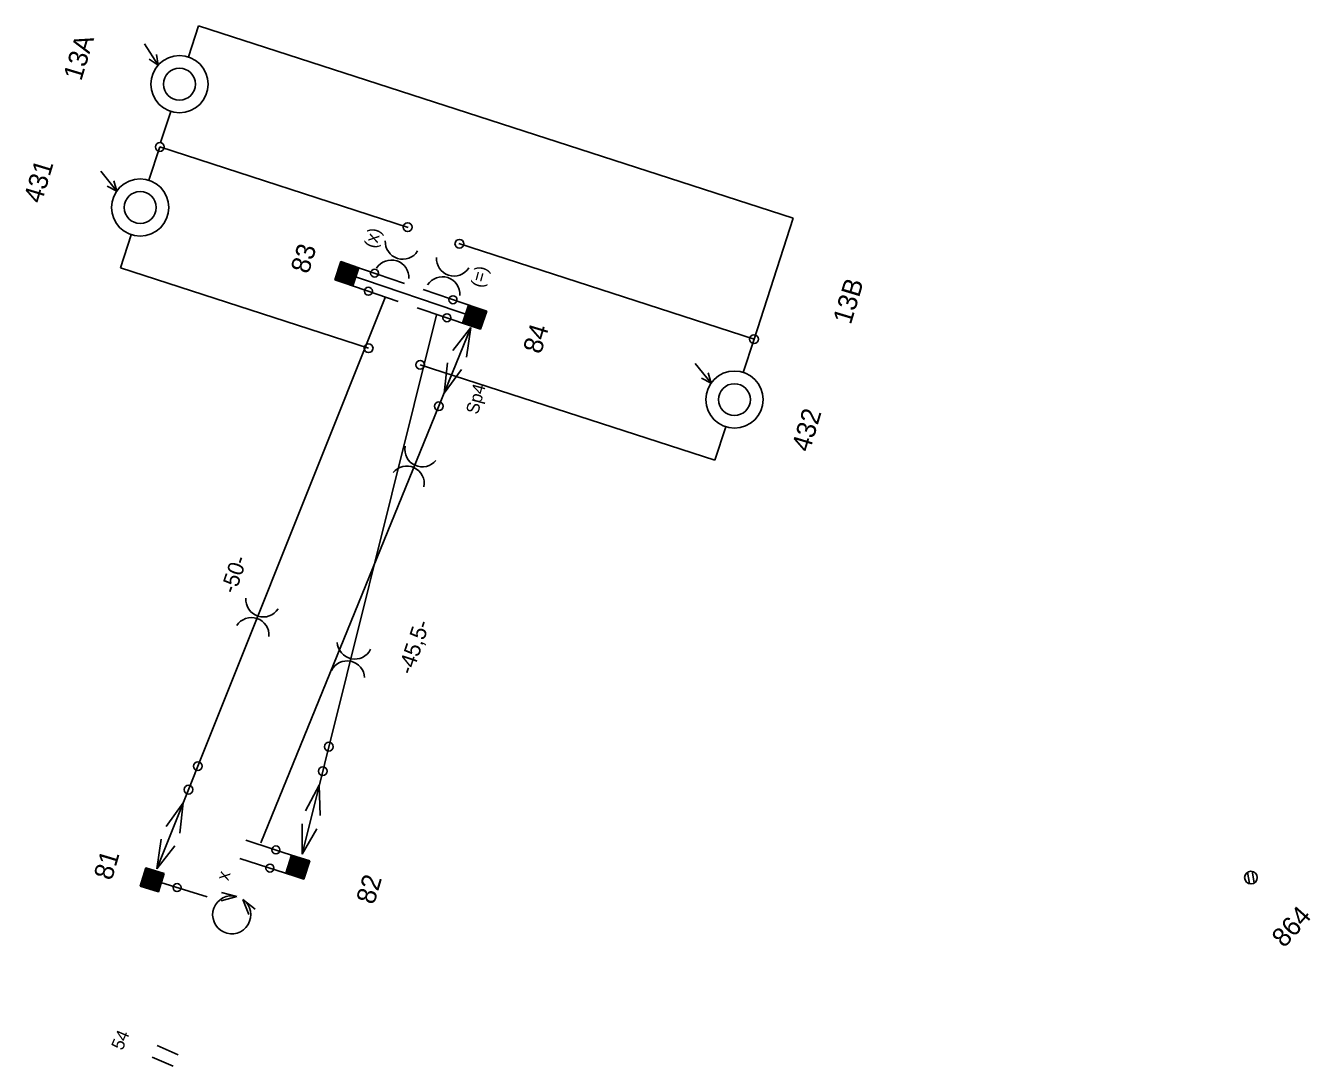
# Model space of a CAD drawing. Extents: x -595867 to -593796, y -1159595 to -1157495.
# Drawn here: x -594654.2 to -594553.2, y -1157682.6 to -1157600.8 of the extents above; entities that cross this region are included whole.
import ezdxf

# ---------------------------------------------------------------- set-up
doc = ezdxf.new("R2010")
doc.units = 0
doc.layers.add('BVK_kanalizace_destova_nova', color=7, linetype='Continuous')
doc.layers.add('BVK_kanalizace_jednotna_nova', color=7, linetype='Continuous')

# ---------------------------------------------------------------- blocks, each defined once
blk = doc.blocks.new('st_bp')
for p, q in [((0.0075, 0.0075), (-0.0075, 0.0075)), ((-0.0075, 0.0075), (-0.0075, -0.0075)), ((-0.0075, -0.0075), (0.0075, 0.0075)), ((-0.0075, -0.0071), (0.0071, 0.0075)), ((-0.0075, -0.0067), (0.0067, 0.0075)), ((-0.0075, -0.0062), (0.0062, 0.0075)), ((-0.0075, -0.0058), (0.0058, 0.0075)), ((-0.0075, -0.0054), (0.0054, 0.0075)), ((-0.0075, -0.005), (0.005, 0.0075)), ((-0.0075, -0.0045), (0.0045, 0.0075)), ((-0.0075, -0.0041), (0.0041, 0.0075)), ((-0.0075, -0.0037), (0.0037, 0.0075)), ((-0.0075, -0.0033), (0.0033, 0.0075)), ((-0.0075, -0.0028), (0.0028, 0.0075)), ((-0.0075, -0.0024), (0.0024, 0.0075)), ((-0.0075, -0.002), (0.002, 0.0075)), ((-0.0075, -0.0016), (0.0016, 0.0075)), ((-0.0075, -0.0011), (0.0011, 0.0075)), ((-0.0075, -0.0007), (0.0007, 0.0075)), ((-0.0075, -0.0003), (0.0003, 0.0075)), ((-0.0075, 0.0001), (-0.0001, 0.0075)), ((-0.0075, 0.0006), (-0.0006, 0.0075)), ((-0.0075, 0.001), (-0.001, 0.0075)), ((-0.0075, 0.0014), (-0.0014, 0.0075)), ((-0.0075, 0.0018), (-0.0018, 0.0075)), ((-0.0075, 0.0023), (-0.0023, 0.0075)), ((-0.0075, 0.0027), (-0.0027, 0.0075)), ((-0.0075, 0.0031), (-0.0031, 0.0075)), ((-0.0075, 0.0035), (-0.0035, 0.0075)), ((-0.0075, 0.004), (-0.004, 0.0075)), ((-0.0075, 0.0044), (-0.0044, 0.0075)), ((-0.0075, 0.0048), (-0.0048, 0.0075)), ((-0.0075, 0.0052), (-0.0052, 0.0075)), ((-0.0075, 0.0057), (-0.0057, 0.0075)), ((-0.0075, 0.0061), (-0.0061, 0.0075)), ((-0.0075, 0.0065), (-0.0065, 0.0075)), ((-0.0075, 0.0069), (-0.0069, 0.0075)), ((-0.0075, 0.0073), (-0.0073, 0.0075)), ((-0.0071, -0.0075), (0.0075, 0.0071)), ((-0.0067, -0.0075), (0.0075, 0.0067)), ((-0.0062, -0.0075), (0.0075, 0.0062)), ((-0.0058, -0.0075), (0.0075, 0.0058)), ((-0.0054, -0.0075), (0.0075, 0.0054)), ((-0.005, -0.0075), (0.0075, 0.005)), ((-0.0045, -0.0075), (0.0075, 0.0045)), ((-0.0041, -0.0075), (0.0075, 0.0041)), ((-0.0037, -0.0075), (0.0075, 0.0037)), ((-0.0033, -0.0075), (0.0075, 0.0033)), ((-0.0028, -0.0075), (0.0075, 0.0028)), ((-0.0024, -0.0075), (0.0075, 0.0024)), ((-0.002, -0.0075), (0.0075, 0.002)), ((-0.0016, -0.0075), (0.0075, 0.0016)), ((-0.0011, -0.0075), (0.0075, 0.0011)), ((-0.0007, -0.0075), (0.0075, 0.0007)), ((-0.0003, -0.0075), (0.0075, 0.0003)), ((0.0075, -0.0075), (0.0075, 0.0075)), ((-0.0075, -0.0075), (0.0075, -0.0075)), ((0.0001, -0.0075), (0.0075, -0.0001)), ((0.0006, -0.0075), (0.0075, -0.0006)), ((0.001, -0.0075), (0.0075, -0.001)), ((0.0014, -0.0075), (0.0075, -0.0014)), ((0.0018, -0.0075), (0.0075, -0.0018)), ((0.0023, -0.0075), (0.0075, -0.0023)), ((0.0027, -0.0075), (0.0075, -0.0027)), ((0.0031, -0.0075), (0.0075, -0.0031)), ((0.0035, -0.0075), (0.0075, -0.0035)), ((0.004, -0.0075), (0.0075, -0.004)), ((0.0044, -0.0075), (0.0075, -0.0044)), ((0.0048, -0.0075), (0.0075, -0.0048)), ((0.0052, -0.0075), (0.0075, -0.0052)), ((0.0057, -0.0075), (0.0075, -0.0057)), ((0.0061, -0.0075), (0.0075, -0.0061)), ((0.0065, -0.0075), (0.0075, -0.0065)), ((0.0069, -0.0075), (0.0075, -0.0069)), ((0.0073, -0.0075), (0.0075, -0.0073))]:
    blk.add_line(p, q)
blk = doc.blocks.new('st_tecka')
blk.add_circle((0, 0), 0.00314)
blk = doc.blocks.new('st1k_bp')
blk.add_line((0, 0), (0.0453, 0))
blk.add_blockref('st_bp', (0, 0))
at = {"rotation": 90}
blk.add_blockref('st_tecka', (0.0205, 0), dxfattribs=at)
blk = doc.blocks.new('st2k_bp')
for p, q in [((0, 0.0075), (0.0453, 0.0075)), ((0, -0.0075), (0.0453, -0.0075))]:
    blk.add_line(p, q)
at = {"rotation": 90}
for p in [(0.0205, 0.0075), (0.0205, -0.0075)]:
    blk.add_blockref('st_tecka', p, dxfattribs=at)
blk.add_blockref('st_bp', (0, 0))
blk = doc.blocks.new('pol_sipk')
for q in [(0.0257, 0.0306), (0.0048, 0.0163), (0.0152, 0.0076)]:
    blk.add_line((0, 0), q)
blk = doc.blocks.new('odp_mzap')
for radius in [0.045, 0.025]:
    blk.add_circle((0, 0), radius)
blk.add_blockref('pol_sipk', (0.0179, 0.0413))
blk = doc.blocks.new('pol_izol')
for centre, start, end in [((-0.0148, 0), 284.4047, 75.5953), ((0.0148, 0), 104.4047, 255.5953)]:
    blk.add_arc(centre, 0.0138, start, end)
blk = doc.blocks.new('kotv_tecka')
blk.add_circle((0, 0), 0.00345)
blk = doc.blocks.new('kotv_poh')
for p, q in [((-0.0558, 0), (-0.0328, 0.0065)), ((-0.0558, 0), (-0.0336, -0.0056)), ((0, 0), (-0.023, -0.0056))]:
    blk.add_line(p, q)
blk.add_lwpolyline([(0, 0), (-0.0221, 0.0064)])
for p in [(-0.087, 0), (-0.0671, 0)]:
    blk.add_blockref('kotv_tecka', p)
blk = doc.blocks.new('pol_sipka2')
for q in [(0.0123, 0.003), (0.0118, -0.0034)]:
    blk.add_line((0, 0), q)
blk = doc.blocks.new('pol_delic')
for p, q in [((-0.005, -0.009), (-0.005, 0.009)), ((0.005, -0.009), (0.005, 0.009))]:
    blk.add_line(p, q)
blk = doc.blocks.new('kotv_polok')
for p, q in [((-0.0558, 0), (-0.0328, 0.0065)), ((-0.0558, 0), (-0.0336, -0.0056)), ((0, 0), (-0.023, -0.0056))]:
    blk.add_line(p, q)
blk.add_lwpolyline([(0, 0), (-0.0221, 0.0064)])
blk.add_blockref('kotv_tecka', (-0.067, 0))
blk = doc.blocks.new('odp_mvyp')
for radius in [0.045, 0.025]:
    blk.add_circle((0, 0), radius)
blk.add_blockref('pol_sipk', (0.0179, 0.0413))

msp = doc.modelspace()

# ---------------------------------------------------------------- linework, layer by layer
at = {"layer": 'BVK_kanalizace_destova_nova'}
for p, q in [((-594641.45, -1157603.25), (-594640.66, -1157600.79)), ((-594593.87, -1157615.93), (-594640.66, -1157600.79)), ((-594643.63, -1157609.99), (-594642.84, -1157607.53)), ((-594644.55, -1157612.95), (-594643.7, -1157610.33)), ((-594643.7, -1157610.33), (-594624.17, -1157616.65)), ((-594596.95, -1157625.45), (-594593.87, -1157615.93)), ((-594646.78, -1157619.84), (-594645.94, -1157617.23)), ((-594596.95, -1157625.45), (-594620.17, -1157617.93)), ((-594627.27, -1157626.16), (-594646.78, -1157619.84)), ((-594625.98, -1157622.18), (-594643.93, -1157667.11)), ((-594621.93, -1157623.52), (-594632.5, -1157665.94)), ((-594635.75, -1157665.06), (-594619.22, -1157624.52)), ((-594597.8, -1157628.06), (-594596.95, -1157625.45)), ((-594623.21, -1157627.46), (-594600.03, -1157634.96)), ((-594600.03, -1157634.96), (-594599.18, -1157632.34))]:
    msp.add_line(p, q, dxfattribs=at)
msp.add_arc((-594638.04, -1157670.72), 1.5, 74.9327, 53.7464, dxfattribs=at)
at = {"layer": 'BVK_kanalizace_jednotna_nova'}
for p, q in [((-594628.35, -1157619.98), (-594629.6, -1157620.63)), ((-594628.85, -1157619.82), (-594629.45, -1157620.12)), ((-594628.51, -1157620.48), (-594629.1, -1157620.79)), ((-594618.3, -1157623.39), (-594619.56, -1157624.03)), ((-594618.8, -1157623.23), (-594619.4, -1157623.53)), ((-594618.47, -1157623.9), (-594619.05, -1157624.19)), ((-594632.72, -1157666.49), (-594633.32, -1157666.79)), ((-594644.17, -1157667.49), (-594644.77, -1157667.79)), ((-594632.22, -1157666.66), (-594633.48, -1157667.29)), ((-594632.39, -1157667.16), (-594632.98, -1157667.45)), ((-594557.97, -1157668.27), (-594558.13, -1157667.37)), ((-594557.6, -1157668.22), (-594557.77, -1157667.3)), ((-594643.67, -1157667.65), (-594644.93, -1157668.29)), ((-594643.83, -1157668.15), (-594644.42, -1157668.45))]:
    msp.add_line(p, q, dxfattribs=at)
for points in [[(-594628.65, -1157620.93), (-594629.61, -1157620.63), (-594629.3, -1157619.67), (-594628.35, -1157619.98)], [(-594618.61, -1157624.34), (-594619.56, -1157624.03), (-594619.25, -1157623.08), (-594618.3, -1157623.39)], [(-594632.53, -1157667.6), (-594633.48, -1157667.29), (-594633.17, -1157666.34), (-594632.22, -1157666.65)], [(-594643.98, -1157668.6), (-594644.93, -1157668.29), (-594644.62, -1157667.34), (-594643.67, -1157667.65)]]:
    msp.add_lwpolyline(points, close=True, dxfattribs=at)
for points in [[(-594628.65, -1157620.93), (-594629.61, -1157620.63), (-594629.3, -1157619.67), (-594628.35, -1157619.98), (-594628.65, -1157620.93)], [(-594628.98, -1157620.3), (-594618.93, -1157623.71)], [(-594618.61, -1157624.34), (-594619.56, -1157624.03), (-594619.25, -1157623.08), (-594618.3, -1157623.39), (-594618.61, -1157624.34)], [(-594632.53, -1157667.6), (-594633.48, -1157667.29), (-594633.17, -1157666.34), (-594632.22, -1157666.65), (-594632.53, -1157667.6)], [(-594643.98, -1157668.6), (-594644.93, -1157668.29), (-594644.62, -1157667.34), (-594643.67, -1157667.65), (-594643.98, -1157668.6)]]:
    msp.add_lwpolyline(points, dxfattribs=at)
msp.add_circle((-594557.86, -1157667.79), 0.5, dxfattribs=at)
msp.add_circle((-594557.86, -1157667.79), 0.5, dxfattribs=at)

# ---------------------------------------------------------------- block references
at = {"layer": 'BVK_kanalizace_destova_nova'}
for name, p, xscale, yscale, rotation in [('odp_mvyp', (-594642.15, -1157605.39), 50.00000000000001, 49.99999999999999, 72.06723553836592), ('kotv_tecka', (-594643.7, -1157610.33), 100, 100, 73.06723553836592), ('odp_mzap', (-594645.24, -1157615.09), 50, 50, 78.51685128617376), ('kotv_tecka', (-594624.2, -1157616.64), 100, 100, 73.06723553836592), ('pol_izol', (-594625.03, -1157619.19), 100.00000000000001, 99.99999999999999, 72.42210460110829), ('kotv_tecka', (-594620.13, -1157617.94), 100, 100, 73.06723553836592), ('st2k_bp', (-594628.98, -1157620.3), 100, 100, -18.916669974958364), ('pol_izol', (-594621.01, -1157620.51), 100.00000000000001, 99.99999999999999, 72.11776305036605), ('st2k_bp', (-594618.93, -1157623.71), 100, 100, 161.3658048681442), ('kotv_polok', (-594619.22, -1157624.52), 100.00000000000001, 99.99999999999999, 67.81291349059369), ('kotv_tecka', (-594596.95, -1157625.45), 100, 100, 73.06723553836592), ('kotv_tecka', (-594627.27, -1157626.16), 100, 100, 73.06723553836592), ('kotv_tecka', (-594623.21, -1157627.46), 100, 100, 73.06723553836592), ('odp_mzap', (-594598.49, -1157630.2), 50, 50, 78.51685128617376), ('pol_izol', (-594623.66, -1157635.46), 100.00000000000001, 99.99999999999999, 65.41114768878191), ('pol_izol', (-594636.02, -1157647.32), 100.00000000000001, 99.99999999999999, 71.52175158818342), ('pol_izol', (-594628.66, -1157650.68), 100.00000000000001, 100, 78.2068989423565), ('kotv_poh', (-594632.5, -1157665.94), 100, 100.00000000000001, -103.99052815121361), ('kotv_poh', (-594643.93, -1157667.11), 100, 100, -111.77753442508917), ('st2k_bp', (-594632.85, -1157666.97), 100, 100, 162.019646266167), ('st1k_bp', (-594644.3, -1157667.97), 100, 99.99999999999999, -17.194787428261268), ('pol_sipka2', (-594637.65, -1157669.27), 99.99999999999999, 100.00000000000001, -177.89011103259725), ('pol_sipka2', (-594637.16, -1157669.51), 100.00000000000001, -99.99999999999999, -54.79401657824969), ('pol_delic', (-594643.28, -1157681.82), 100, 100, 66.27836083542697)]:
    msp.add_blockref(name, p, dxfattribs=dict(at, xscale=xscale, yscale=yscale, rotation=rotation))

# ---------------------------------------------------------------- texts
for s, height, rotation, p in [('13A', 1.5, 73.2592, (-594649.88, -1157605.19)), ('431', 1.5, 73.2592, (-594653.01, -1157614.84)), ('(x)', 1, 74.9481, (-594626.69, -1157618.36)), ('83', 1.5, 73.2592, (-594632, -1157620.37)), ('(=)', 1, 74.9481, (-594618.3, -1157621.46)), ('13B', 1.5, 73.2592, (-594589.34, -1157624.36)), ('84', 1.5, 73.2592, (-594613.72, -1157626.68)), ('Sp4', 1, 74.9481, (-594618.67, -1157631.42)), ('432', 1.5, 73.2592, (-594592.59, -1157634.39)), ('-50-', 1.25, 71.1841, (-594637.76, -1157645.54)), ('-45,5-', 1.25, 71.1841, (-594623.84, -1157651.91)), ('81', 1.5, 73.2592, (-594647.49, -1157668.08)), ('x', 1, 74.9481, (-594638.3, -1157668.09)), ('82', 1.5, 73.2592, (-594626.85, -1157669.98)), ('54', 1, 66.9347, (-594646.64, -1157681.44))]:
    msp.add_text(s, height=height, rotation=rotation, dxfattribs=at).set_placement(p)
at = {"layer": 'BVK_kanalizace_jednotna_nova'}
msp.add_text('864', height=1.5, rotation=48.37, dxfattribs=at).set_placement((-594555.24, -1157673.38))

doc.saveas('drawing.dxf')
